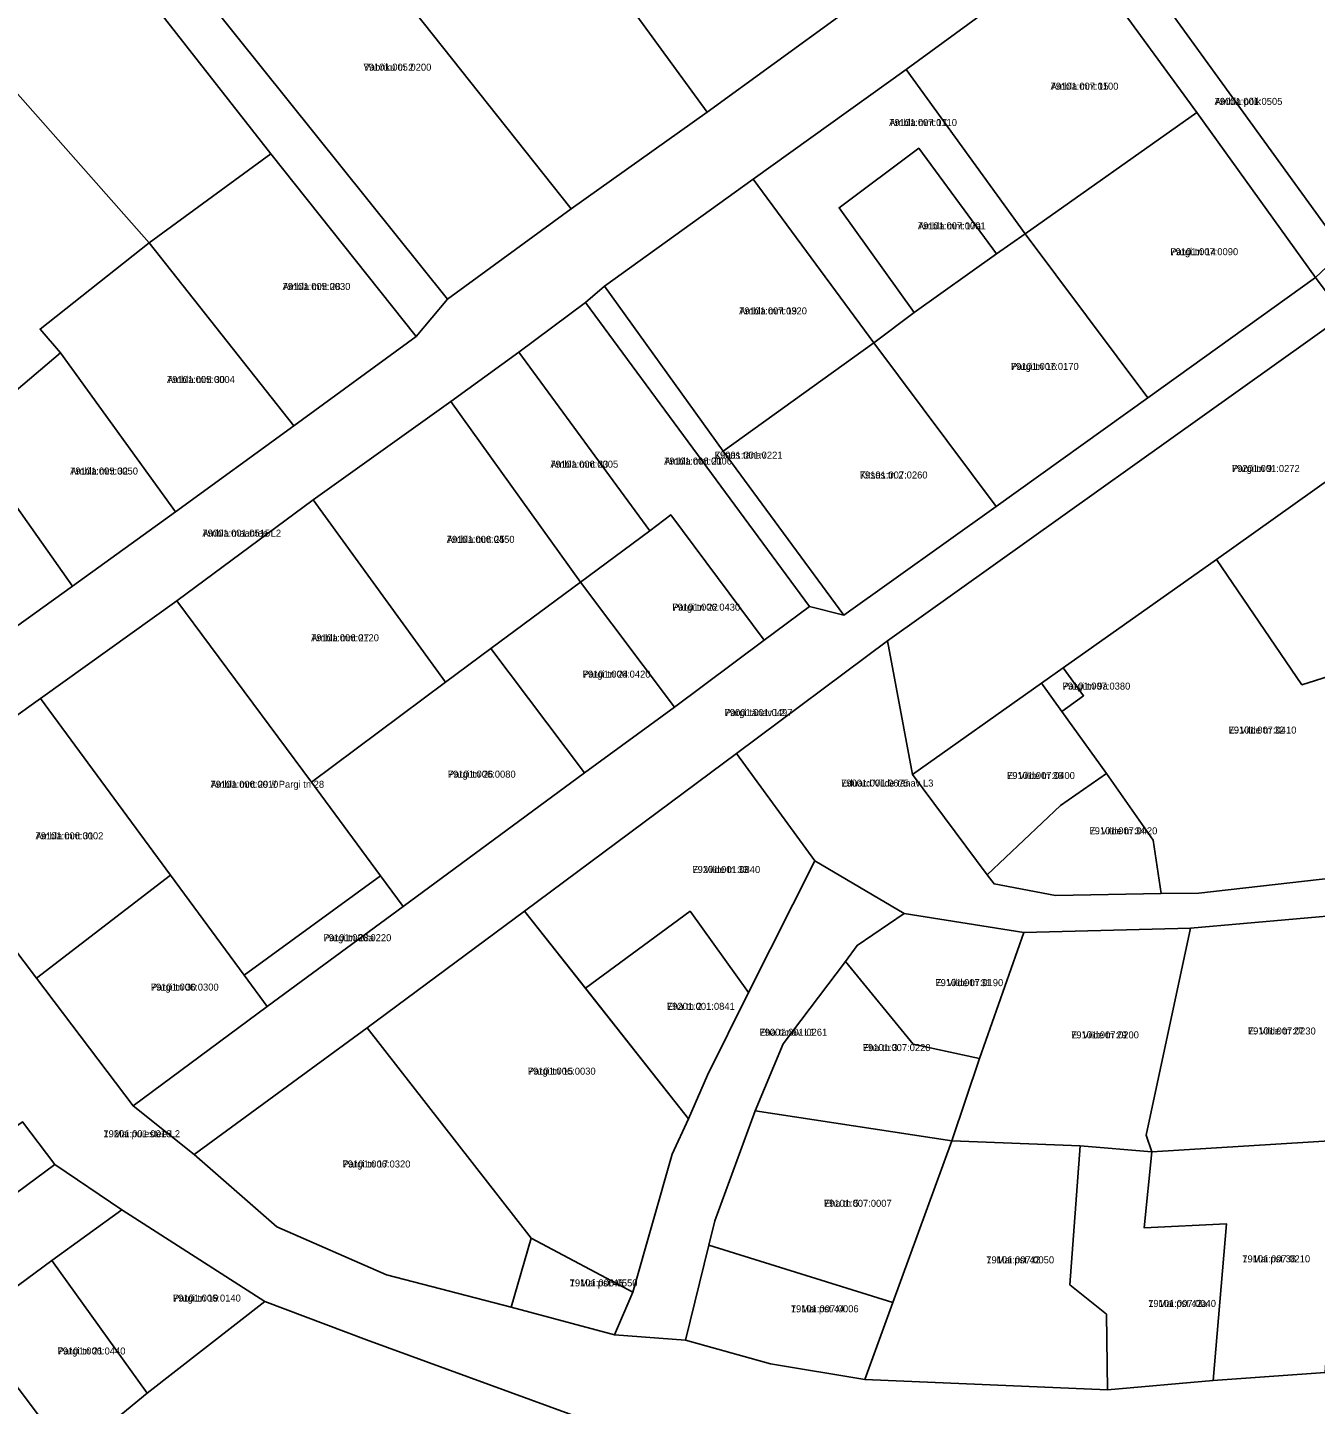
# Model space of a CAD drawing. Extents: x 587616 to 632239, y 6547421 to 6574977.
# Drawn here: x 611171.2 to 611446.6, y 6570695.1 to 6570989.5 of the extents above; entities that cross this region are included whole.
import ezdxf

# ---------------------------------------------------------------- set-up
doc = ezdxf.new("R2010")
doc.units = 0
for name, color, linetype in [('L_AADRESS', 7, 'Continuous'), ('PIIR', 7, 'Continuous'), ('TUNNUS', 7, 'Continuous')]:
    doc.layers.add(name, color=color, linetype=linetype)

msp = doc.modelspace()

# ---------------------------------------------------------------- linework, layer by layer
at = {"layer": 'PIIR'}
for points in [[(611556.99, 6571124.68), (611590.3, 6571148.55), (611614.86, 6571115.38), (611639.31, 6571081.15), (611617.76, 6571067.56), (611574.16, 6571034.86), (611564.19, 6571024.58), (611454.85, 6570943.73), (611452.04, 6570944.05), (611449.7, 6570945.77), (611402.13, 6571011.47), (611505.14, 6571086.78)], [(611156.66, 6571070.28), (611154.58, 6571064.79), (611198.68, 6571009.17), (611261.02, 6570931.41), (611254.31, 6570923.41), (611223.25, 6570962.49), (611165.61, 6571036.08), (611157.51, 6571046.24), (611143.8, 6571063.34), (611133.8, 6571071.36)], [(611304.49, 6571048.96), (611315.07, 6571034.19), (611300.33, 6571023.41), (611319.66, 6570996.74), (611334.38, 6571007.24), (611345.18, 6570992.17), (611316.55, 6570971.35), (611270.09, 6571035.03), (611284.4, 6571040.8)], [(611197.21, 6570943.4), (611164.71, 6570980.12), (611135.09, 6571013.58), (611165.61, 6571036.08), (611223.25, 6570962.49)], [(611270.09, 6571035.03), (611316.55, 6570971.35), (611287.47, 6570950.69), (611232.48, 6571020.02), (611255.8, 6571029.3)], [(611228.73, 6571029.46), (611232.48, 6571020.02), (611287.47, 6570950.69), (611261.02, 6570931.41), (611198.68, 6571009.17)], [(611178.29, 6570919.9), (611157.83, 6570902.59), (611114.51, 6570959.96), (611120.56, 6570964.17), (611116.71, 6570969.36), (611143.5, 6570975.57), (611135.09, 6571013.58), (611164.71, 6570980.12), (611197.21, 6570943.4), (611173.91, 6570925)], [(611395.22, 6571006.93), (611402.13, 6571011.47), (611449.7, 6570945.77), (611452.04, 6570944.05), (611454.85, 6570943.73), (611446.63, 6570935.99), (611421.24, 6570971.29)], [(611359.13, 6570980.51), (611395.22, 6571006.93), (611421.24, 6570971.29), (611384.57, 6570945.39)], [(611360.84, 6570928.57), (611352.2, 6570922.03), (611326.35, 6570957.07), (611359.13, 6570980.51), (611384.57, 6570945.39), (611378.41, 6570941.05), (611361.79, 6570963.66), (611344.77, 6570950.93)], [(611410.78, 6570910.3), (611384.57, 6570945.39), (611421.24, 6570971.29), (611446.63, 6570935.99)], [(611254.31, 6570923.41), (611228.2, 6570904.31), (611197.21, 6570943.4), (611223.25, 6570962.49)], [(611361.79, 6570963.66), (611378.41, 6570941.05), (611360.84, 6570928.57), (611344.77, 6570950.93)], [(611294.56, 6570934.2), (611326.35, 6570957.07), (611352.2, 6570922.03), (611319.99, 6570898.9)], [(611360.46, 6570829.79), (611355.11, 6570858.39), (611452.66, 6570927.93), (611494.74, 6570959.13), (611500.63, 6570956.37), (611504.31, 6570932.12), (611489.87, 6570921.94), (611454.42, 6570896.33), (611425.42, 6570875.77), (611392.67, 6570852.6), (611388.01, 6570849.3)], [(611352.2, 6570922.03), (611360.84, 6570928.57), (611378.41, 6570941.05), (611384.57, 6570945.39), (611410.78, 6570910.3), (611378.34, 6570887.06)], [(611197.21, 6570943.4), (611228.2, 6570904.31), (611202.84, 6570885.91), (611178.29, 6570919.9), (611173.91, 6570925)], [(611410.78, 6570910.3), (611446.63, 6570935.99), (611452.66, 6570927.93), (611355.11, 6570858.39), (611322.85, 6570834.25), (611277.47, 6570800.56), (611243.83, 6570775.62), (611206.86, 6570748.58), (611193.85, 6570758.95), (611222.49, 6570780.17), (611251.52, 6570801.55), (611290.35, 6570830.17), (611309.54, 6570844.16), (611328.74, 6570858.49), (611338.4, 6570865.67), (611345.77, 6570863.86), (611378.34, 6570887.06)], [(611290.55, 6570930.69), (611294.56, 6570934.2), (611319.99, 6570898.9), (611345.77, 6570863.86), (611338.4, 6570865.67)], [(611276.28, 6570920.05), (611290.55, 6570930.69), (611338.4, 6570865.67), (611328.74, 6570858.49), (611308.77, 6570885.31), (611304.31, 6570881.88)], [(611319.99, 6570898.9), (611352.2, 6570922.03), (611378.34, 6570887.06), (611345.77, 6570863.86)], [(611202.84, 6570885.91), (611180.84, 6570870.03), (611157.83, 6570902.59), (611178.29, 6570919.9)], [(611276.28, 6570920.05), (611304.31, 6570881.88), (611289.45, 6570870.91), (611261.73, 6570909.52)], [(611261.73, 6570909.52), (611289.45, 6570870.91), (611270.32, 6570856.7), (611260.58, 6570849.51), (611232.27, 6570888.51)], [(611180.84, 6570870.03), (611134.78, 6570837), (611110.71, 6570868.83), (611157.83, 6570902.59)], [(611454.42, 6570896.33), (611476.44, 6570865.26), (611477.17, 6570859.56), (611458.32, 6570853.56), (611443.72, 6570848.96), (611425.42, 6570875.77)], [(611203.14, 6570866.88), (611232.27, 6570888.51), (611260.58, 6570849.51), (611231.98, 6570828.17)], [(611289.45, 6570870.91), (611304.31, 6570881.88), (611308.77, 6570885.31), (611328.74, 6570858.49), (611309.54, 6570844.16)], [(611413.65, 6570804.38), (611411.88, 6570815.74), (611401.9, 6570830.04), (611392.36, 6570843.26), (611397.04, 6570846.62), (611392.67, 6570852.6), (611425.42, 6570875.77), (611443.72, 6570848.96), (611458.32, 6570853.56), (611463.72, 6570809.2), (611421.69, 6570804.42)], [(611289.45, 6570870.91), (611309.54, 6570844.16), (611290.35, 6570830.17), (611270.32, 6570856.7)], [(611173.98, 6570846.02), (611203.14, 6570866.88), (611231.98, 6570828.17), (611246.7, 6570808.15), (611217.56, 6570786.89), (611201.82, 6570808.25)], [(611246.7, 6570808.15), (611231.98, 6570828.17), (611260.58, 6570849.51), (611270.32, 6570856.7), (611290.35, 6570830.17), (611251.52, 6570801.55)], [(611322.85, 6570834.25), (611355.11, 6570858.39), (611360.46, 6570829.79), (611376.44, 6570808.33), (611377.88, 6570806.42), (611391, 6570803.96), (611413.65, 6570804.38), (611421.69, 6570804.42), (611463.72, 6570809.2), (611485.96, 6570812.06), (611521.46, 6570816.68), (611523.18, 6570808.97), (611485.59, 6570803.86), (611453.91, 6570799.95), (611419.86, 6570796.94), (611384.28, 6570796.03), (611358.69, 6570800.05), (611339.59, 6570811.31)], [(611392.67, 6570852.6), (611397.04, 6570846.62), (611392.36, 6570843.26), (611388.01, 6570849.3)], [(611360.46, 6570829.79), (611388.01, 6570849.3), (611392.36, 6570843.26), (611401.9, 6570830.04), (611392.11, 6570823.17), (611376.44, 6570808.33)], [(611173.98, 6570846.02), (611201.82, 6570808.25), (611173.18, 6570786.28), (611144.06, 6570824.65)], [(611290.5, 6570784.1), (611277.47, 6570800.56), (611322.85, 6570834.25), (611339.59, 6570811.31), (611325.41, 6570783.22), (611312.88, 6570800.57)], [(611377.88, 6570806.42), (611376.44, 6570808.33), (611392.11, 6570823.17), (611401.9, 6570830.04), (611411.88, 6570815.74), (611413.65, 6570804.38), (611391, 6570803.96)], [(611339.59, 6570811.31), (611358.69, 6570800.05), (611348.59, 6570793.25), (611346.13, 6570789.83), (611332.83, 6570772.22), (611326.79, 6570757.87), (611318.17, 6570734.37), (611316.9, 6570729.22), (611311.91, 6570708.9), (611296.76, 6570710.01), (611300.62, 6570719.17), (611309.09, 6570748.61), (611312.58, 6570756.2), (611316.64, 6570765.56), (611325.41, 6570783.22)], [(611173.18, 6570786.28), (611201.82, 6570808.25), (611217.56, 6570786.89), (611222.49, 6570780.17), (611193.85, 6570758.95)], [(611217.56, 6570786.89), (611246.7, 6570808.15), (611251.52, 6570801.55), (611222.49, 6570780.17)], [(611278.93, 6570730.72), (611243.83, 6570775.62), (611277.47, 6570800.56), (611312.58, 6570756.2), (611309.09, 6570748.61), (611300.62, 6570719.17)], [(611312.58, 6570756.2), (611290.5, 6570784.1), (611312.88, 6570800.57), (611325.41, 6570783.22), (611316.64, 6570765.56)], [(611374.8, 6570769.06), (611360.6, 6570772.17), (611346.13, 6570789.83), (611348.59, 6570793.25), (611358.69, 6570800.05), (611384.28, 6570796.03)], [(611410.44, 6570752.71), (611419.86, 6570796.94), (611453.91, 6570799.95), (611451.97, 6570751.62), (611411.66, 6570749.17)], [(611368.87, 6570751.51), (611374.8, 6570769.06), (611384.28, 6570796.03), (611419.86, 6570796.94), (611410.44, 6570752.71), (611411.66, 6570749.17), (611396.28, 6570750.4)], [(611346.13, 6570789.83), (611360.6, 6570772.17), (611374.8, 6570769.06), (611368.87, 6570751.51), (611326.79, 6570757.87), (611332.83, 6570772.22)], [(611206.86, 6570748.58), (611243.83, 6570775.62), (611278.93, 6570730.72), (611274.66, 6570715.97), (611247.98, 6570722.86), (611224.54, 6570733.13)], [(611326.79, 6570757.87), (611368.87, 6570751.51), (611356.25, 6570716.91), (611316.9, 6570729.22), (611318.17, 6570734.37)], [(611135.65, 6570730.24), (611170.18, 6570755.52), (611177.06, 6570746.46), (611142.57, 6570720.92)], [(611368.87, 6570751.51), (611396.28, 6570750.4), (611394.08, 6570720.74), (611401.95, 6570714.41), (611402.18, 6570698.3), (611350.28, 6570700.48), (611356.25, 6570716.91)], [(611427.61, 6570733.72), (611409.98, 6570732.9), (611411.66, 6570749.17), (611451.97, 6570751.62), (611448.71, 6570701.95), (611424.73, 6570700.25)], [(611402.18, 6570698.3), (611401.95, 6570714.41), (611394.08, 6570720.74), (611396.28, 6570750.4), (611411.66, 6570749.17), (611409.98, 6570732.9), (611427.61, 6570733.72), (611424.73, 6570700.25)], [(611177.06, 6570746.46), (611191.36, 6570736.72), (611176.43, 6570725.91), (611158.5, 6570712.73), (611123.05, 6570686.65), (611050.46, 6570634.89), (611041.87, 6570614.48), (611015.81, 6570639.45), (611057.75, 6570668.09), (611062.75, 6570661.25), (611089.74, 6570681.78), (611105.52, 6570692.61), (611116.04, 6570700.62), (611129.18, 6570710.82), (611142.57, 6570720.92)], [(611221.94, 6570717.14), (611196.81, 6570697.55), (611176.43, 6570725.91), (611191.36, 6570736.72)], [(611278.93, 6570730.72), (611300.62, 6570719.17), (611296.76, 6570710.01), (611274.66, 6570715.97)], [(611316.9, 6570729.22), (611356.25, 6570716.91), (611350.25, 6570700.46), (611330.07, 6570703.81), (611311.91, 6570708.9)], [(611176.43, 6570725.91), (611196.81, 6570697.55), (611180.29, 6570683.96), (611158.5, 6570712.73)], [(611060.3, 6570602.62), (611142.17, 6570660.1), (611180.29, 6570683.96), (611196.81, 6570697.55), (611221.94, 6570717.14), (611243.67, 6570708.96), (611291.51, 6570691.51), (611273.49, 6570614.99), (611255.02, 6570536.33), (611188.45, 6570546.16), (611134.42, 6570561.16), (611095.24, 6570580.14)], [(611123.05, 6570686.65), (611158.5, 6570712.73), (611180.29, 6570683.96), (611142.17, 6570660.1)]]:
    msp.add_lwpolyline(points, close=True, dxfattribs=at)
for points in [[(611134.78, 6570837), (611180.84, 6570870.03), (611202.84, 6570885.91), (611228.2, 6570904.31), (611254.31, 6570923.41), (611261.02, 6570931.41), (611287.47, 6570950.69), (611316.55, 6570971.35), (611345.18, 6570992.17), (611361.36, 6571004.06), (611373.31, 6571012.84), (611395.22, 6571006.93), (611359.13, 6570980.51), (611326.35, 6570957.07), (611294.56, 6570934.2), (611290.55, 6570930.69), (611276.28, 6570920.05), (611261.73, 6570909.52), (611232.27, 6570888.51), (611203.14, 6570866.88), (611173.98, 6570846.02), (611144.06, 6570824.65)], [(611144.06, 6570824.65), (611173.18, 6570786.28), (611193.85, 6570758.95), (611206.86, 6570748.58), (611224.54, 6570733.13), (611247.98, 6570722.86), (611274.66, 6570715.97), (611296.76, 6570710.01), (611311.91, 6570708.9), (611330.07, 6570703.81), (611350.28, 6570700.48), (611402.18, 6570698.3), (611424.73, 6570700.25), (611448.71, 6570701.95), (611493.19, 6570709.17), (611530.28, 6570716.77), (611538.86, 6570718.6), (611555.59, 6570725.99), (611562.63, 6570707.5), (611544.29, 6570701.99), (611515.53, 6570692.73)], [(611291.51, 6570691.51), (611243.67, 6570708.96), (611221.94, 6570717.14), (611191.36, 6570736.72), (611177.06, 6570746.46), (611170.18, 6570755.52)]]:
    msp.add_lwpolyline(points, dxfattribs=at)

# ---------------------------------------------------------------- texts
at = {"layer": 'L_AADRESS'}
for s, p in [('Vabriku tn 2', (611243.07, 6570980.23)), ('Ambla mnt 15', (611389.98, 6570976.16)), ('Ambla põik', (611425.04, 6570972.92)), ('Ambla mnt 17', (611355.46, 6570968.41)), ('Ambla mnt 17a', (611361.59, 6570946.31)), ('Pargi tn 14', (611415.59, 6570940.79)), ('Ambla mnt 28', (611225.76, 6570933.36)), ('Ambla mnt 19', (611323.38, 6570928.13)), ('Pargi tn 16', (611381.49, 6570916.27)), ('Ambla mnt 30', (611201.05, 6570913.47)), ('Ambla mnt 21', (611307.34, 6570896.04)), ('Kitsas tänav', (611318.16, 6570897.31)), ('Ambla mnt 32', (611180.34, 6570893.91)), ('Ambla mnt 23', (611283.02, 6570895.37)), ('Pargi tn 9', (611428.75, 6570894.46)), ('Kitsas tn 2', (611349.17, 6570893.06)), ('Ambla maantee L2', (611208.61, 6570880.64)), ('Ambla mnt 25', (611260.86, 6570879.31)), ('Pargi tn 22', (611309.1, 6570864.81)), ('Ambla mnt 27', (611231.86, 6570858.27)), ('Pargi tn 24', (611289.93, 6570850.5)), ('Pargi tn 9a', (611392.52, 6570847.94)), ('Pargi tänav L2', (611320.28, 6570842.28)), ('E. Vilde tn 32', (611428.04, 6570838.54)), ('Pargi tn 26', (611261.1, 6570829.12)), ('E. Vilde tn 36', (611380.67, 6570828.82)), ('Ambla mnt 29 // Pargi tn 28', (611210.34, 6570826.95)), ('Eduard Vilde tänav L3', (611345.18, 6570827.21)), ('E. Vilde tn 34', (611398.3, 6570817)), ('Ambla mnt 31', (611172.94, 6570815.94)), ('E. Vilde tn 33', (611313.39, 6570808.74)), ('Pargi tn 28a', (611234.51, 6570794.16)), ('E. Vilde tn 31', (611365.35, 6570784.55)), ('Pargi tn 30', (611197.59, 6570783.6)), ('Eha tn 2', (611307.95, 6570779.49)), ('Eha tänav L1', (611327.72, 6570773.95)), ('E. Vilde tn 29', (611394.36, 6570773.38)), ('E. Vilde tn 27', (611432.17, 6570774.22)), ('Eha tn 3', (611349.81, 6570770.67)), ('Pargi tn 15', (611278.2, 6570765.64)), ('1. Mai puiestee L2', (611187.45, 6570752.26)), ('Pargi tn 17', (611238.6, 6570745.79)), ('Eha tn 5', (611341.5, 6570737.39)), ('1. Mai pst 38', (611430.97, 6570725.52)), ('1. Mai pst 42', (611376.23, 6570725.3)), ('1. Mai pst 46', (611287.15, 6570720.37)), ('Pargi tn 19', (611202.33, 6570717.13)), ('1. Mai pst 44', (611334.43, 6570714.84)), ('1. Mai pst 42a', (611410.84, 6570715.99)), ('Pargi tn 21', (611177.66, 6570705.82))]:
    msp.add_text(s, height=1.5, dxfattribs=at).set_placement(p)
at = {"layer": 'TUNNUS'}
for s, p in [('79101:005:0200', (611243.07, 6570980.23)), ('79101:007:0100', (611389.98, 6570976.16)), ('79001:001:0505', (611425.04, 6570972.92)), ('79101:007:0110', (611355.46, 6570968.41)), ('79101:007:0001', (611361.59, 6570946.31)), ('79101:007:0090', (611415.59, 6570940.79)), ('79101:005:0030', (611225.76, 6570933.36)), ('79101:007:0320', (611323.38, 6570928.13)), ('79101:007:0170', (611381.49, 6570916.27)), ('79101:005:0004', (611201.05, 6570913.47)), ('79001:001:0221', (611318.16, 6570897.31)), ('79101:005:0050', (611180.34, 6570893.91)), ('79101:006:0005', (611283.02, 6570895.37)), ('79101:006:0006', (611307.34, 6570896.04)), ('79201:001:0272', (611428.75, 6570894.46)), ('79101:007:0260', (611349.17, 6570893.06)), ('79001:001:0515', (611208.61, 6570880.64)), ('79101:006:0450', (611260.86, 6570879.31)), ('79101:006:0430', (611309.1, 6570864.81)), ('79101:006:0120', (611231.86, 6570858.27)), ('79101:006:0420', (611289.93, 6570850.5)), ('79101:007:0380', (611392.52, 6570847.94)), ('79001:001:0497', (611320.28, 6570842.28)), ('79101:007:0410', (611428.04, 6570838.54)), ('79101:006:0080', (611261.1, 6570829.12)), ('79101:007:0400', (611380.67, 6570828.82)), ('79101:006:0010', (611210.34, 6570826.95)), ('79001:001:0675', (611345.18, 6570827.21)), ('79101:007:0420', (611398.3, 6570817)), ('79101:006:0002', (611172.94, 6570815.94)), ('79201:001:0840', (611313.39, 6570808.74)), ('79101:006:0220', (611234.51, 6570794.16)), ('79101:007:0190', (611365.35, 6570784.55)), ('79101:006:0300', (611197.59, 6570783.6)), ('79201:001:0841', (611307.95, 6570779.49)), ('79001:001:0261', (611327.72, 6570773.95)), ('79101:007:0200', (611394.36, 6570773.38)), ('79101:007:0230', (611432.17, 6570774.22)), ('79101:007:0220', (611349.81, 6570770.67)), ('79101:006:0030', (611278.2, 6570765.64)), ('79201:001:0016', (611187.45, 6570752.26)), ('79101:006:0320', (611238.6, 6570745.79)), ('79101:007:0007', (611341.5, 6570737.39)), ('79101:007:0210', (611430.97, 6570725.52)), ('79101:007:0050', (611376.23, 6570725.3)), ('79101:006:0550', (611287.15, 6570720.37)), ('79101:006:0140', (611202.33, 6570717.13)), ('79101:007:0006', (611334.43, 6570714.84)), ('79101:007:0040', (611410.84, 6570715.99)), ('79101:006:0440', (611177.66, 6570705.82))]:
    msp.add_text(s, height=1.5, dxfattribs=at).set_placement(p)

doc.saveas('drawing.dxf')
